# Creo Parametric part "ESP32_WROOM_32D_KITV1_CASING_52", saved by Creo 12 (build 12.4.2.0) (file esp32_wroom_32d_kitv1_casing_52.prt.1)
Units: Custom; MM, KILOGRAM, SECS

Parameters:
  PTC_WM_ITERATION = "0"
  PTC_WM_VERSION = "-.0"
  PTC_WM_LIFECYCLE_STATE = "In Work"
  PTC_WM_LIFECYCLE = "MO_CADDocument"
  PTC_WM_CREATED_BY = "Maximilian Roepper (Z0017RMS: MO)"
  PTC_WM_CREATED_ON = "18-Sep-26 11:36:42 AM"
  PTC_WM_MODIFIED_BY = "Maximilian Roepper (Z0017RMS: MO)"
  PTC_WM_MODIFIED_ON = "18-Sep-26 11:36:46 AM"
  PDMLINKNUMBER = "PDM000071454969"
  PTC_WM_NAME = "esp32_wroom_32d_kitv1_casing_52.prt"
  PTC_WM_NUMBER = "PDM000071454969"

Other parameters: WEIGHT, WEIGHT_FACTOR, WEIGHT_ADD, _MASS_TEMP, _DIFF_TEMP, MC_ERRORS, SUPPLIER

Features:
  1. coordinate system
  2. datum plane "PRT_YZ"
  3. datum plane "PRT_XY"
  4. datum plane "PRT_XZ"
  5. coordinate system
  6. datum axis
  7. datum axis
  8. datum axis
  9. coordinate system
  10. imported feature
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
Other named items: PRT, SIEMENS_MO, DRW_VIEW_ORG, PRT_X, PRT_Y, PRT_Z, CS0, ROUGH_GROB

Layers: 00_STD_CSYS-KSYS, 01_STD_PLANES-EBENEN, 02_STD_AXES-ACHSEN, 03_STD_CSYS-KSYS, 24_IMPORT_FEAT-IMPORT_KE

Surfaces: 5 plane, 1 cylinder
